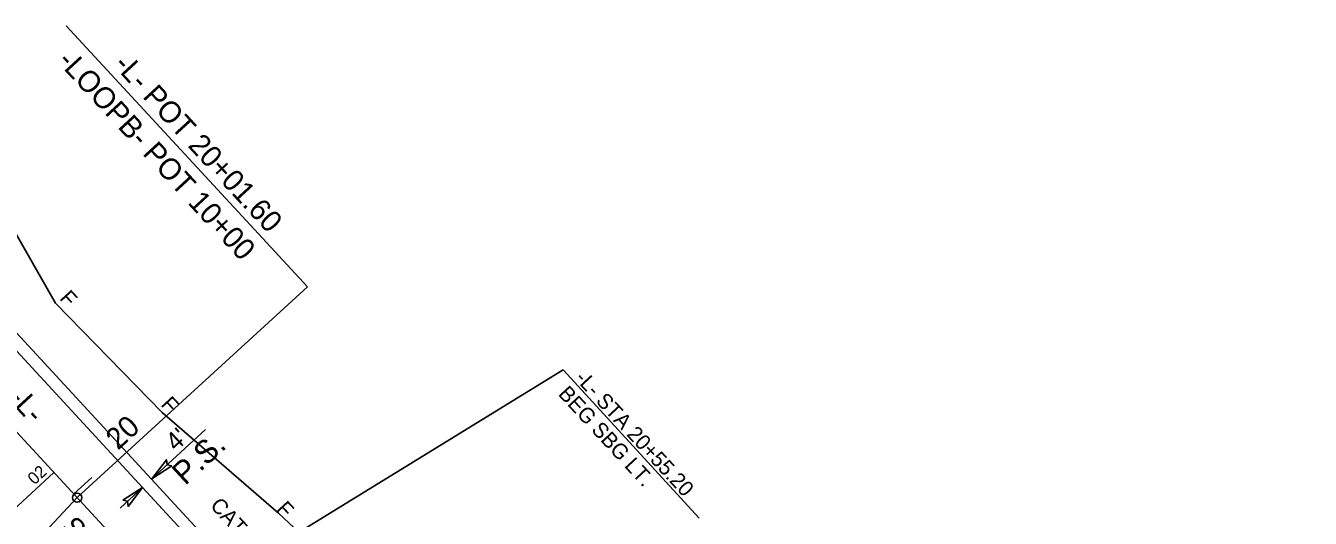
# Model space of a CAD drawing. Extents: x 1702862 to 1704514, y 793768 to 796215.
# Drawn here: x 1703316.6 to 1703737.1, y 795219.2 to 795380.5 of the extents above; entities that cross this region are included whole.
import ezdxf

# ---------------------------------------------------------------- set-up
doc = ezdxf.new("R2010")
doc.units = 0
for name, color, linetype in [('Prop Dimension', 7, 'Continuous'), ('Prop Dimension Text', 7, 'Continuous'), ('Prop DSN Text', 7, 'Continuous'), ('Prop EOT', 7, 'Continuous'), ('Prop Guardrail Anchor Unit CELL', 7, 'Continuous'), ('Prop Horizontal Alignment', 7, 'Continuous'), ('Prop Horizontal Alignment Direction Label', 7, 'Continuous'), ('Prop Horizontal Alignment Station Label', 7, 'Continuous'), ('Prop Horizontal Alignment Tick Label', 7, 'Continuous'), ('Prop Horizontal Alignment Tick Large', 7, 'Continuous'), ('Prop Leader Line Medium', 7, 'Continuous'), ('Prop Paved Shoulder', 7, 'Continuous'), ('Prop SS Fill Line', 7, 'Continuous'), ('Prop SS Misc', 7, 'Continuous'), ('Prop SS Transition Line', 7, 'Continuous'), ('Prop Superelevation  Arrow CELL', 7, 'Continuous'), ('Prop Superelevation Label', 7, 'Continuous'), ('Prop Terminator CELL', 7, 'Continuous')]:
    doc.layers.add(name, color=color, linetype=linetype)

msp = doc.modelspace()

# ---------------------------------------------------------------- linework, layer by layer
at = {"layer": 'Prop Dimension'}
for p, q in [((1703357.93, 795232.14), (1703375.41, 795248.29)), ((1703347.52, 795222.54), (1703354.84, 795229.3))]:
    msp.add_line(p, q, dxfattribs=at)
at = {"layer": 'Prop EOT'}
msp.add_line((1703259.9, 795332.15), (1703737.14, 794815.13), dxfattribs=at)
at = {"layer": 'Prop Horizontal Alignment'}
for p, q in [((1703246.67, 795319.94), (1703723.92, 794802.92)), ((1703333.42, 795225.96), (1703157.53, 795038.5))]:
    msp.add_line(p, q, dxfattribs=at)
at = {"layer": 'Prop Horizontal Alignment Station Label'}
for p in [(1703329.85, 795380.52), (1703333.42, 795225.96)]:
    msp.add_line(p, (1703408.81, 795294.97), dxfattribs=at)
msp.add_circle((1703333.42, 795225.96), 1.5, dxfattribs=at)
at = {"layer": 'Prop Horizontal Alignment Tick Large'}
msp.add_line((1703332.34, 795227.14), (1703338.22, 795232.56), dxfattribs=at)
at = {"layer": 'Prop Leader Line Medium'}
for q in [(1703388.7, 795204.04), (1703537.12, 795219.21)]:
    msp.add_line((1703492.5, 795267.75), q, dxfattribs=at)
at = {"layer": 'Prop Paved Shoulder'}
msp.add_line((1703262.84, 795334.86), (1703385.95, 795201.5), dxfattribs=at)
at = {"layer": 'Prop SS Fill Line'}
for p, q in [((1703326.3, 795289.61), (1703361.26, 795253.83)), ((1703361.26, 795253.83), (1703399.32, 795220.91)), ((1703399.32, 795220.91), (1703435.98, 795186.71))]:
    msp.add_line(p, q, dxfattribs=at)
at = {"layer": 'Prop SS Transition Line'}
msp.add_line((1703300.88, 795334.19), (1703326.3, 795289.61), dxfattribs=at)
at = {"layer": 'Prop Superelevation  Arrow CELL'}
msp.add_line((1703325.81, 795234.21), (1703312.58, 795222), dxfattribs=at)
at = {"layer": 'Prop Terminator CELL'}
for points in [[(1703364.44, 795236.36), (1703357.93, 795232.14), (1703362.66, 795238.36), (1703362.86, 795236.7)], [(1703348.33, 795225.08), (1703354.84, 795229.3), (1703350.11, 795223.08), (1703349.91, 795224.74)]]:
    msp.add_lwpolyline(points, close=True, dxfattribs=at)

# ---------------------------------------------------------------- texts
at = {"layer": 'Prop Dimension Text'}
for s, height, rotation, p in [('-L- STA 20+55.20', 5, 312.7091, (1703496.17, 795264.8)), ('BEG SBG LT.', 5, 312.7091, (1703490.66, 795259.71)), ("4'", 6, 42.7091, (1703365.75, 795240.82))]:
    msp.add_text(s, height=height, rotation=rotation, dxfattribs=at).set_placement(p)
at = {"layer": 'Prop DSN Text'}
msp.add_text('P.S.', height=7.5, rotation=42.7091, dxfattribs=at).set_placement((1703368.79, 795229.7))
at = {"layer": 'Prop Guardrail Anchor Unit CELL'}
msp.add_text('CAT-1', height=5, rotation=312.7301, dxfattribs=at).set_placement((1703376.71, 795223.13))
at = {"layer": 'Prop Horizontal Alignment Direction Label'}
for s, p in [('-L-', (1703310.6, 795258.2)), ('S 42%%d 42\' 32.6" E', (1703327.66, 795215.83))]:
    msp.add_text(s, height=7, rotation=312.7091, dxfattribs=at).set_placement(p)
at = {"layer": 'Prop Horizontal Alignment Station Label'}
for s, p in [('-LOOPB- POT 10+00', (1703326.69, 795368.67)), ('-L- POT 20+01.60', (1703345.07, 795367.46))]:
    msp.add_text(s, height=7, rotation=312.7091, dxfattribs=at).set_placement(p)
at = {"layer": 'Prop Horizontal Alignment Tick Label'}
msp.add_text('20', height=7, rotation=42.7091, dxfattribs=at).set_placement((1703346.79, 795241.28))
at = {"layer": 'Prop SS Misc'}
for p in [(1703327.43, 795291.03), (1703360.58, 795256.25), (1703398.36, 795221.96)]:
    msp.add_text('F', height=5, rotation=312.7091, dxfattribs=at).set_placement(p)
at = {"layer": 'Prop Superelevation Label'}
msp.add_text('02', height=4, rotation=42.7091, dxfattribs=at).set_placement((1703319.46, 795229.94))

doc.saveas('drawing.dxf')
